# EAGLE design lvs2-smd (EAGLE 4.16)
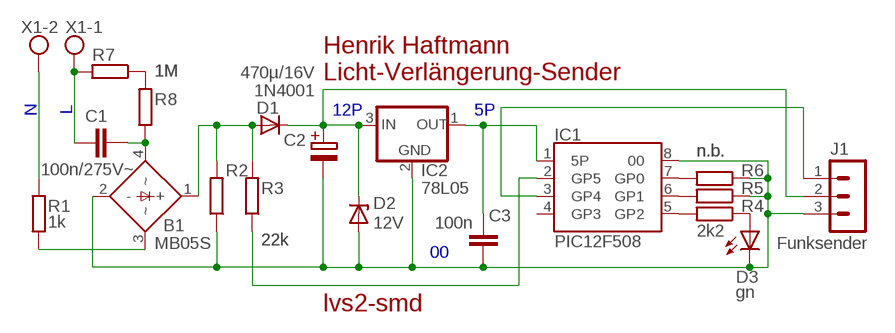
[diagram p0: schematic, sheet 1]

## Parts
B1  MB05S  DBM  [DBS]
C1  100n/275V~  C15  [C150-084X183]
C2  470µ/16V  E02-10  [E02-10]
C3  100n  C0805  [0805]
D1  1N4001  D  [MINIMELF]
D2  12V  DZ1206  [1206]
D3  gn  LED0805  [0805]
IC1  PIC12F508  PIC12FJ  [SO8]
IC2  78L05  78XX89  [SOT89]
J1  Funksender  MA03-1  [MA03-1]
R1  1k  R02  [R02]
R2  22k  R0805  [0805]
R3  22k  R0805  [0805]
R4  2k2  R0805  [0805]
R5  n.b.  R0805  [0805]
R6  n.b.  R0805  [0805]
R7  1M  R1206  [1206]
R8  1M  R1206  [1206]
X1  W237-02P  [W237-132]

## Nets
00: B1.2(-) C2.- C3.2 D2.1(A) D3.2(K) IC1.8 IC2.2(GND) J1.3 R2.1 R5.1 R6.1
5P: C3.1 IC1.1(5P) IC2.1(OUT)
12P: C2.+ D1.K D2.2(K) IC2.3(IN) J1.2
!ZC: IC1.2(GP5) R3.1
L: C1.1 R7.2 X1.1
N: R1.2 X1.2
N$1: B1.4(~) C1.2 R8.1
N$2: IC1.3(GP4) J1.1
N$3: B1.1(+) D1.A R2.2 R3.2
N$4: B1.3(~) R1.1
N$5: IC1.5(GP2) R4.2
N$6: D3.1(A) R4.1
N$7: IC1.6(GP1) R5.2
N$8: IC1.7(GP0) R6.2
N$9: R7.1 R8.2
Unconnected: IC1.4(GP3)

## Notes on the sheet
- Henrik Haftmann
- Licht-Verlängerung-Sender

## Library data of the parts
B1 = fu:DB: Gleichrichterbrücke 1-phasig Typliste TypSpannungStromGehäuse MB05S..MB10S50..1000 V0,5 AMBS, e=2,5mm
C1 C3 = fu:C: Kondensator
C2 = fu:E: Elektrolytkondensator, gepolt
D1 = fu:D: Diode
D2 = fu:DZ: Z-Diode
D3 = fu:LED: Leuchtdiode
IC1 = fu:PIC12F*: 8-Bit-Mikrocontroller mit 8 Beinchen TypFlashRAMEEPROMADC 12F508
IC2 = fu:78XX: Spannungsregler positiv (78xx) oder negativ (79xx)
J1 = con-lstb:MA03-1: PIN HEADER
R1-R8 = fu:R: Widerstand
X1 = con-wago-508:W237-02P: WAGO SREW CLAMP

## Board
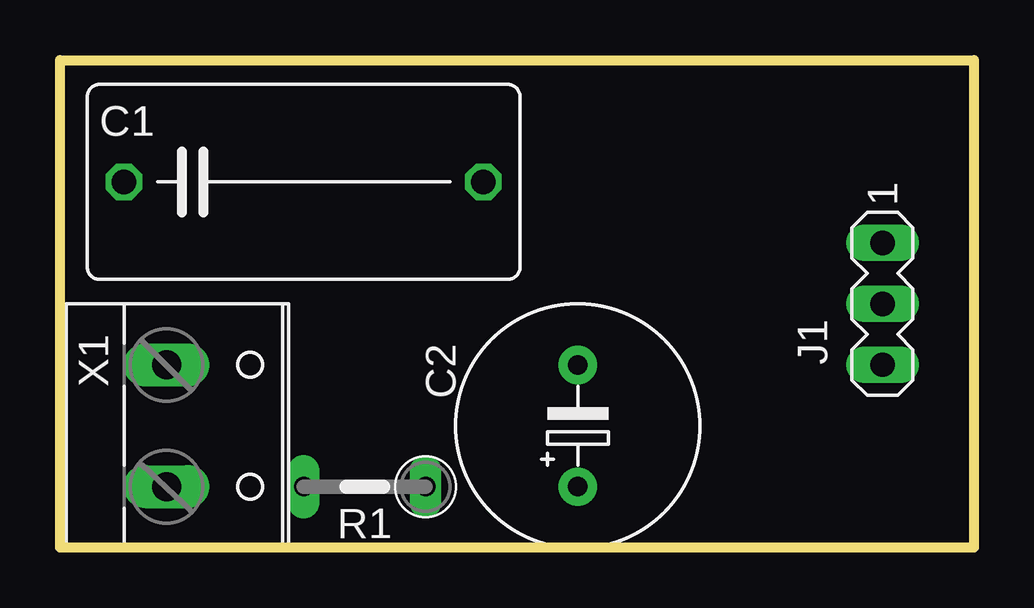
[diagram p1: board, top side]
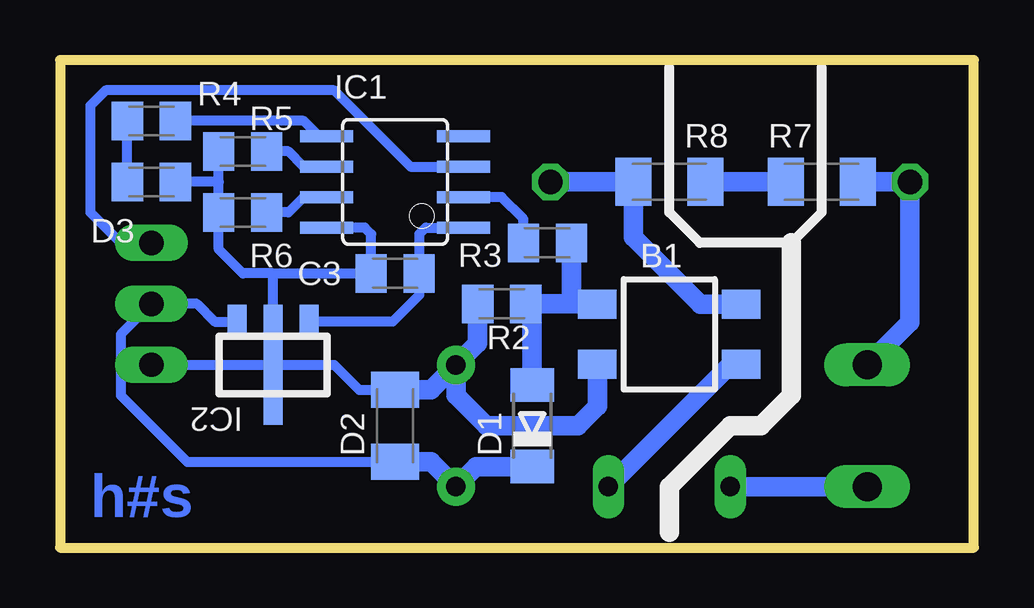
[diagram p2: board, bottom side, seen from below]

Size 38.1 x 20.32 mm. Coordinates in mm from the lower left corner, seen from the top.
Outline: 0,20.32 38.1,20.32 38.1,0 0,0 0,20.32
Copper layers 16: Bottom 0.035mm
Design rules "default": minimum track width 10mil, minimum drill 0.6mm, track to track 8mil, track to pad 8mil, pad to pad 8mil, via to via 8mil, smd to smd 0mil, copper to edge 0.5mm, drill to drill 8mil, minimum pad ring 10mil, minimum via ring 8mil, stop-mask expansion 4mil, vias tented up to drill 0mil, thermal gap 10mil

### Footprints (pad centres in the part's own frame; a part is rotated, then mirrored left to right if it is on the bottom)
DBS = smd 1.2 x 1.6: 1 -1.25,-3; 2 1.25,-3; 3 1.25,3; 4 -1.25,3
C150-084X183 = drill 1.016 octagon: 1 -7.493,0; 2 7.493,0
E02-10 = drill 0.813 pad 1.6 round: + -2.54,0; - 2.54,0
0805 = smd 1.3 x 1.6: 1 -1,0; 2 1,0
MINIMELF = smd 1.4 x 1.8: A 1.7,0; K -1.7,0
1206 = smd 1.5 x 2: 1 -1.5,0; 2 1.5,0
SO8 = smd 0.5 x 2.2: 1 -1.905,-2.857; 2 -0.635,-2.857; 3 0.635,-2.857; 4 1.905,-2.857; 5 1.905,2.857; 6 0.635,2.857; 7 -0.635,2.857; 8 -1.905,2.857
SOT89 = smd 0.8 x 1.4: 1 -1.5,-1.8; 3 1.5,-1.8 | smd 0.8 x 5: 2 0,0
MA03-1 = drill 1.016 long: 1 -2.54,0; 2 0,0; 3 2.54,0
R02 = drill 0.813 long: 1 -2.54,0; 2 2.54,0
W237-132 = drill 1.194 long: 1 -2.54,-0.635; 2 2.54,-0.635

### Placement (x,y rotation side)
B1  12.7,8.89 270 bottom
C1  10.16,15.24 0 top
C2  21.59,5.08 90 top
C3  24.13,11.43 180 bottom
D1  18.41,5.08 90 bottom
D2  24.13,5.08 270 bottom
D3  34.29,15.24 0 bottom
IC1  24.13,15.24 90 bottom
IC2  29.21,7.62 180 bottom
J1  34.29,10.16 270 top
R1  12.7,2.54 180 top
R2  19.68,10.16 0 bottom
R3  17.78,12.7 0 bottom
R4  34.29,17.78 0 bottom
R5  30.48,16.51 0 bottom
R6  30.48,13.97 0 bottom
R7  6.35,15.24 0 bottom
R8  12.7,15.24 0 bottom
X1  5.08,5.08 270 top

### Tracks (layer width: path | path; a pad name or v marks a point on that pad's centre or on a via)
00
  Bottom 0.406: 29.21,11.43 C3.2 25.13,13.06 25.4,13.34 IC1.8 | IC2.2 29.21,11.43 | J1.3 IC2.2 | 24.13,6.35 D2.1 25.63,6.58 26.67,7.62 IC2.2 | 31.48,15.24 R5.1 | 31.48,15.24 R6.1 31.48,12.43 30.48,11.43 29.21,11.43 | 31.48,15.24 D3.2
  Bottom 0.813: R2.1 20.68,8.53 C2.- | D2.1 22.63,6.58 C2.- | C2.- 21.59,6.35 20.32,5.08 16.51,5.08 15.7,5.89 B1.2
5P
  Bottom 0.406: IC2.1 24.23,9.42 23.5,10.16 | 23.5,10.16 23.27,10.39 | IC1.1 22.86,13.34 23.13,13.06 C3.1 23.13,10.53 23.5,10.16
12P
  Bottom 0.406: IC2.3 31.64,9.42 32.38,10.16 J1.2 35.56,8.89 35.56,6.35 32.79,3.58 D2.2
  Bottom 0.813: D1.K 20.75,3.38 C2.+ 22.63,3.58 D2.2
!ZC
  Bottom 0.406: IC1.2 19.68,14.61 18.78,13.7 R3.1
L
  Bottom 0.813: C1.1 2.67,9.4 X1.1 | C1.1 2.54,15.24 | C1.1 R7.2
N
  Bottom 0.813: R1.2 X1.2
N$1
  Bottom 0.813: R8.1 13.97,15.24 | R8.1 C1.2 | B1.4 11.41,10.14 14.2,12.93 R8.1
N$2
  Bottom 0.406: J1.1 35.56,12.7 36.83,13.97 36.83,18.41 36.2,19.05 26.67,19.05 23.5,15.88 IC1.3
N$3
  Bottom 0.406: 18.41,10.16 R2.2 | B1.1 16.49,10.14 16.51,10.16
  Bottom 0.813: D1.A 18.41,10.16 17.14,10.16 | 16.51,10.16 17.14,10.16 | R3.2 16.78,10.16 17.14,10.16
N$4
  Bottom 0.813: B1.3 10.14,7.64 R1.1
N$5
  Bottom 0.406: IC1.5 27.3,17.14 27.94,17.78 R4.2
N$6
  Bottom 0.406: D3.1 R4.1
N$7
  Bottom 0.406: R5.2 28.57,16.51 27.94,15.88 IC1.6
N$8
  Bottom 0.406: R6.2 28.57,13.97 27.94,14.61 IC1.7
N$9
  Bottom 0.813: 11.43,15.24 R8.2 R7.1

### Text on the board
Bottom: h#s
Measures: 20,32 = 0.8" | 38,1 = 1.5"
